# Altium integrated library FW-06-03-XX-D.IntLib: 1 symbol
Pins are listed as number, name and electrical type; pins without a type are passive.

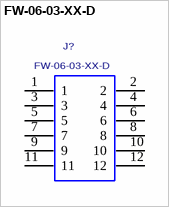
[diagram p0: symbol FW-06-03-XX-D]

## FW-06-03-XX-D
designator J?
.050 x .050 SURFACE MOUNT BOARD SPACERS, 12 PINS.; MANUFACTURER: SAMTEC
footprint FW-06-03-XX-D
pins: 1, 2, 3, 4, 5, 6, 7, 8, 9, 10, 11, 12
